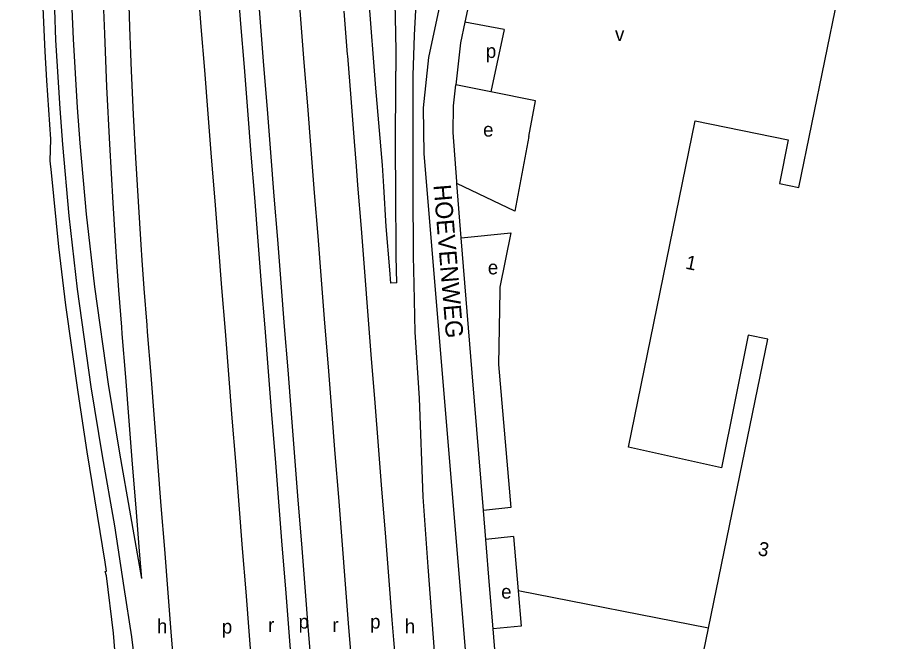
# Model space of a CAD drawing. Extents: x 157699 to 159683, y 381451 to 383293.
# Drawn here: x 157749.4 to 157997.9, y 381952.4 to 382131.3 of the extents above; entities that cross this region are included whole.
import ezdxf

# ---------------------------------------------------------------- set-up
doc = ezdxf.new("R2010")
doc.units = 0
for name, color, linetype in [('BLT_Basislijn', 7, 'Continuous'), ('BLT_Bebouwing', 7, 'Continuous'), ('BLT_Centroide', 7, 'Continuous'), ('BLT_Gemeentegrens', 7, 'Continuous'), ('BLT_Huisnummer_reeks', 7, 'Continuous'), ('BLT_Straatnaam', 7, 'Continuous')]:
    doc.layers.add(name, color=color, linetype=linetype)

msp = doc.modelspace()

# ---------------------------------------------------------------- linework, layer by layer
at = {"layer": 'BLT_Basislijn'}
for p, q in [((157878.62, 382134.87), (157877.6, 382129.97)), ((157888.86, 382127.82), (157877.6, 382129.97)), ((157888.86, 382127.82), (157885, 382109.98)), ((157885, 382109.98), (157874.96, 382111.98)), ((157897.79, 382107.44), (157885, 382109.98)), ((157895.88, 382097.22), (157897.79, 382107.44)), ((157875.31, 382083.71), (157875.26, 382084.32)), ((157876.57, 382068.12), (157875.31, 382083.71)), ((157879.71, 382029.43), (157876.57, 382068.12)), ((157882.92, 381990), (157879.71, 382029.43)), ((157890.81, 381990.78), (157882.92, 381990)), ((157883.59, 381981.69), (157882.92, 381990)), ((157891.53, 381982.48), (157883.59, 381981.69)), ((157884.66, 381968.5), (157883.59, 381981.69)), ((157885.68, 381956.04), (157884.66, 381968.5)), ((157947.41, 381956.21), (157892.89, 381966.89)), ((157893.77, 381956.84), (157885.68, 381956.04)), ((157886.35, 381947.73), (157885.68, 381956.04))]:
    msp.add_line(p, q, dxfattribs=at)
for points in [[(157750.5, 382344.24), (157752.94, 382335.63), (157754.63, 382327.44), (157756.28, 382317.48), (157757.3, 382310.67), (157758.01, 382305.19), (157759.19, 382293.36), (157761.46, 382265.01), (157762.69, 382244.97), (157763.52, 382225.23), (157764.04, 382204.75), (157764.16, 382184.51), (157764.15, 382164.51), (157764.33, 382153.87), (157764.58, 382144.76), (157764.99, 382133.79), (157765.34, 382125.1), (157766.55, 382105.53), (157767.26, 382095.3), (157769.13, 382074.95), (157771.51, 382054.04), (157775.38, 382026.18), (157778.6, 382006.44), (157784.9, 381970.44)], [(157854.01, 382088.97), (157852.13, 382111.04), (157850.07, 382137.09), (157849.3, 382145.82), (157848.34, 382158.92), (157847.61, 382170.98), (157847.53, 382172.31), (157846.82, 382183.47), (157845.99, 382195.97), (157845.11, 382208.46), (157844.18, 382220.95), (157843.86, 382225.17), (157843.85, 382225.36), (157843.22, 382233.44), (157842.2, 382245.92), (157841.15, 382258.4), (157840.67, 382263.8)], [(157870.06, 381934.31), (157867.05, 381973.8), (157865.68, 381993.87), (157864.55, 382022.12), (157863.4, 382041.04), (157863.08, 382054.8), (157862.87, 382062.83), (157862.77, 382082.25), (157862.74, 382092.84), (157862.8, 382114.69), (157863.2, 382126.22), (157863.95, 382140.63), (157864.47, 382147.95), (157865.05, 382154.36), (157865.43, 382160.91), (157865.68, 382167.86), (157865.71, 382188.66), (157865.51, 382224.16), (157865.78, 382227.21), (157866.65, 382230.22), (157867.7, 382231.89), (157870.66, 382235.92)], [(157853.57, 382226.38), (157854.37, 382185.85), (157857.21, 382147.08), (157857.64, 382131.31), (157857.83, 382121.86), (157857.84, 382115.92)], [(157865.93, 382092.23), (157865.77, 382105.36), (157867.28, 382119.86), (157878.1, 382170.39), (157879.03, 382174.64)], [(157833.81, 381943.04), (157832.83, 381955.5), (157831.84, 381967.96), (157830.86, 381980.42), (157829.87, 381992.88), (157828.89, 382005.35), (157827.9, 382017.81), (157826.92, 382030.27), (157825.93, 382042.73), (157824.95, 382055.19), (157823.96, 382067.65), (157822.98, 382080.11), (157821.99, 382092.57), (157821, 382105.03), (157820.02, 382117.5), (157819.03, 382129.96), (157818.05, 382142.42)], [(157829.51, 382143.32), (157830.5, 382130.86), (157831.48, 382118.4), (157832.47, 382105.94), (157833.45, 382093.48), (157834.44, 382081.02), (157835.43, 382068.56), (157836.41, 382056.1), (157837.4, 382043.64), (157838.38, 382031.17), (157839.37, 382018.71), (157840.35, 382006.25), (157841.34, 381993.79), (157842.32, 381981.33), (157843.31, 381968.87), (157844.29, 381956.41), (157845.28, 381943.95)], [(157773.78, 382140.51), (157774.31, 382126.57), (157774.96, 382111.39), (157775.77, 382094.95), (157776.71, 382078.13), (157777.51, 382065.61), (157777.81, 382061.24), (157778.39, 382053.1), (157779.21, 382042.48), (157779.35, 382040.6), (157780.34, 382028.14), (157781.33, 382015.68), (157782.31, 382003.22), (157783.3, 381990.75), (157784.28, 381978.29), (157784.9, 381970.44)], [(157781.1, 382140.99), (157781.51, 382128.5), (157781.8, 382120.86), (157782, 382116.01), (157782.57, 382103.53), (157783.22, 382091.04), (157783.94, 382078.57), (157784.74, 382066.1), (157785.04, 382061.74), (157785.62, 382053.63), (157786.43, 382043.05), (157786.58, 382041.17), (157787.57, 382028.71), (157788.55, 382016.25), (157789.54, 382003.79), (157790.52, 381991.33), (157791.51, 381978.86), (157792.49, 381966.4), (157793.48, 381953.94), (157794.46, 381941.48)], [(157801, 382141.07), (157801.99, 382128.61), (157802.97, 382116.15), (157803.96, 382103.69), (157804.94, 382091.23), (157805.93, 382078.76), (157806.91, 382066.3), (157807.9, 382053.84), (157808.88, 382041.38), (157809.87, 382028.92), (157810.86, 382016.46), (157811.84, 382004), (157812.83, 381991.54), (157813.81, 381979.08), (157814.8, 381966.61), (157815.78, 381954.15), (157816.77, 381941.69)], [(157828.23, 381942.6), (157827.25, 381955.06), (157826.26, 381967.52), (157825.28, 381979.98), (157824.29, 381992.44), (157823.31, 382004.9), (157822.32, 382017.37), (157821.33, 382029.83), (157820.35, 382042.29), (157819.36, 382054.75), (157818.38, 382067.21), (157817.39, 382079.67), (157816.41, 382092.13), (157815.42, 382104.59), (157814.44, 382117.05), (157813.45, 382129.52), (157812.47, 382141.98)], [(157759.99, 382133.6), (157760.34, 382124.84), (157761.56, 382105.2), (157762.28, 382094.9), (157764.15, 382074.44), (157766.55, 382053.42), (157770.43, 382025.44), (157773.67, 382005.6), (157777.17, 381985.59)], [(157842.94, 382133.11), (157843.9, 382120.64), (157843.92, 382120.31), (157844.88, 382108.18), (157845.87, 382095.72), (157846.42, 382088.72), (157846.85, 382083.26), (157847.84, 382070.8), (157848.82, 382058.34), (157849.81, 382045.88), (157850.79, 382033.41), (157851.78, 382020.95), (157851.79, 382020.8), (157852.76, 382008.49), (157853.75, 381996.03), (157854.73, 381983.57), (157855.72, 381971.11), (157856.71, 381958.65), (157857.16, 381952.88), (157857.69, 381946.19)], [(157877.6, 382129.97), (157876.35, 382124), (157874.96, 382111.98)], [(157858.07, 382055.27), (157857.87, 382062.75), (157857.77, 382082.23), (157857.74, 382092.83), (157857.8, 382114.78), (157857.84, 382115.92)], [(157875.26, 382084.32), (157874.28, 382098.3), (157874.38, 382105.95), (157874.96, 382111.98)], [(157895.88, 382097.22), (157891.89, 382075.75), (157875.31, 382083.71)], [(157890.71, 381788.57), (157881.79, 381901.93), (157865.93, 382092.23)], [(157856.35, 382055.13), (157856.05, 382058.91), (157855.06, 382071.37), (157854.41, 382082.87), (157854.01, 382088.97)], [(157876.57, 382068.12), (157890.73, 382069.53), (157887.62, 382053.98), (157887.6, 382052.95)], [(157858.07, 382055.27), (157856.35, 382055.13)], [(157887.6, 382052.95), (157887.23, 382031.82), (157890.81, 381990.78)], [(157777.17, 381985.59), (157779.91, 381967.9), (157782.03, 381953.71), (157783.5, 381941.99), (157784.77, 381930.34), (157786.03, 381916.92), (157786.85, 381906.41), (157787.93, 381893.2), (157788.96, 381879.81), (157790.06, 381866.4), (157792.11, 381840.1), (157794.2, 381813.47), (157795.32, 381799.46), (157797.34, 381773.96), (157799.47, 381750.35), (157800.68, 381738.99), (157802.74, 381724.81), (157806.1, 381703.5), (157809.24, 381684.74), (157813.48, 381660.81)], [(157891.53, 381982.48), (157892.89, 381966.89)], [(157892.89, 381966.89), (157893.77, 381956.84)]]:
    msp.add_lwpolyline(points, dxfattribs=at)
at = {"layer": 'BLT_Bebouwing'}
msp.add_line((157973.28, 382082.59), (157986.71, 382148.21), dxfattribs=at)
for points in [[(157964.37, 382039.09), (157958.8, 382040.19), (157951.13, 382002.23), (157924.45, 382008.14), (157943.56, 382101.7), (157970.24, 382096.24), (157967.73, 382083.67), (157973.28, 382082.59)], [(157947.41, 381956.21), (157956.37, 382000), (157964.37, 382039.09)], [(157997.87, 381910.61), (157945.37, 381921.28), (157940.47, 381922.28), (157947.41, 381956.21)]]:
    msp.add_lwpolyline(points, dxfattribs=at)
at = {"layer": 'BLT_Gemeentegrens'}
for points in [[(157774.52, 381975.12), (157769.41, 382006.76), (157766.75, 382023.87), (157763.24, 382048.83), (157761.3, 382065.53), (157759.11, 382086.81), (157758.79, 382090.22), (157758.94, 382096.45), (157757.81, 382113.2), (157757.32, 382121.56), (157756.54, 382138.36), (157755.86, 382163.54), (157755.77, 382171.94), (157755.9, 382188.37), (157755.78, 382204.45), (157755.47, 382220.5), (157754.8, 382237.26), (157753.48, 382259.91), (157752.84, 382270.77), (157751.46, 382287.51), (157750.73, 382295.87), (157749.7, 382304.21), (157749.37, 382307.22)], [(157821.62, 381457.57), (157813.89, 381461.78), (157813.54, 381462.57), (157812.82, 381466.24), (157811.88, 381479.42), (157808.82, 381528.32), (157802.33, 381638.43), (157799.33, 381669.9), (157791.09, 381758.11), (157790.95, 381765.11), (157790.89, 381768.47), (157790.24, 381786.83), (157790.21, 381787.45), (157789.89, 381794.11), (157787.02, 381829.01), (157779.86, 381917.92), (157776.96, 381954.82), (157774.91, 381971.23), (157774.54, 381972.47), (157774.93, 381972.56), (157774.52, 381975.12)]]:
    msp.add_lwpolyline(points, dxfattribs=at)

# ---------------------------------------------------------------- texts
at = {"layer": 'BLT_Centroide'}
for s, p in [('v', (157920.62, 382124.54)), ('p', (157883.61, 382119.69)), ('e', (157882.82, 382097.15)), ('e', (157884.18, 382057.65)), ('e', (157888, 381964.69)), ('h', (157789.37, 381954.79)), ('p', (157829.95, 381956.1)), ('p', (157850.44, 381956.1)), ('h', (157860.38, 381954.79)), ('p', (157807.96, 381954.67)), ('r', (157821.23, 381955.16)), ('r', (157839.6, 381955.16))]:
    msp.add_text(s, height=4, dxfattribs=at).set_placement(p)
at = {"layer": 'BLT_Huisnummer_reeks'}
for s, p in [('1', (157940.61, 382059.31)), ('3', (157961.34, 381977.21))]:
    msp.add_text(s, height=4, rotation=348.5057, dxfattribs=at).set_placement(p)
at = {"layer": 'BLT_Straatnaam'}
msp.add_text('HOEVENWEG', height=5, rotation=274.7126, dxfattribs=at).set_placement((157868.6, 382083.23))

doc.saveas('drawing.dxf')
